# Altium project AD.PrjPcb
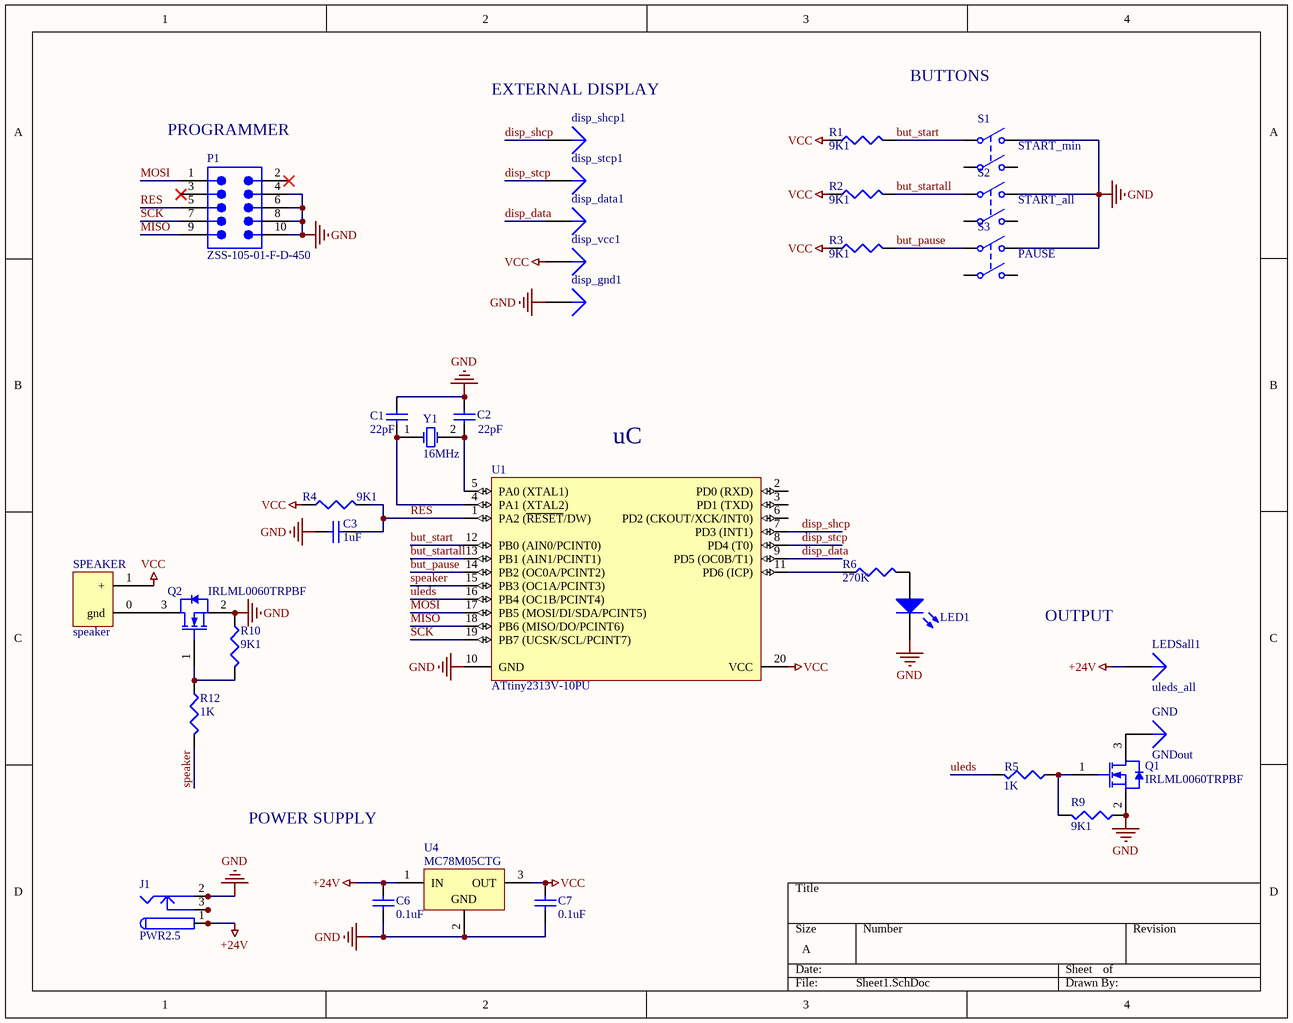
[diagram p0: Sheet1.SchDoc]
1 sheet, 33 parts. Net scope: global (net labels, ports and power ports of the same name join across sheets).
Board file: PCB1.PcbDoc

## Sheet Sheet1.SchDoc
size A

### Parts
C1  value 22pF  [CAPC1608L]  (hidden comment: Cap Semi)
C2  value 22pF  [CAPC1608L]  (hidden comment: Cap Semi)
C3  value 1uF  [CAPC1608L]  (hidden comment: Cap Semi)
C6  value 0.1uF  [CAPC1608L]  (hidden comment: Cap Semi)
C7  value 0.1uF  [CAPC1608L]  (hidden comment: Cap Semi)
disp_data1  uleds_all  [PIN1]  (value not drawn)
disp_gnd1  uleds_all  [PIN1]  (value not drawn)
disp_shcp1  uleds_all  [PIN1]  (value not drawn)
disp_stcp1  uleds_all  [PIN1]  (value not drawn)
disp_vcc1  uleds_all  [PIN1]  (value not drawn)
GND  GNDout  [PIN1]
J1  PWR2.5  [PCBComponent_1]
LED1  151051YS04000  [Type 5mm]  (value not drawn)
LEDSall1  uleds_all  [PIN1]
P1  ZSS-105-01-F-D-450  [SMTC-ZSS-105-01-X-D-450]
Q1  IRLML0060TRPBF  [NXP-SOT23_L]
Q2  IRLML0060TRPBF  [NXP-SOT23_L]
R1  value 9K1  [CAPC1608L]  (hidden comment: Res3)
R2  value 9K1  [CAPC1608L]  (hidden comment: Res3)
R3  value 9K1  [CAPC1608L]  (hidden comment: Res3)
R4  value 9K1  [CAPC1608L]  (hidden comment: Res3)
R5  value 1K  [CAPC1608L]  (hidden comment: Res3)
R6  value 270K  [CAPC1608L]  (hidden comment: Res3)
R9  value 9K1  [CAPC1608L]  (hidden comment: Res3)
R10  value 9K1  [CAPC1608L]  (hidden comment: Res3)
R12  value 1K  [CAPC1608L]  (hidden comment: Res3)
S1  START_min  [key]
S2  START_all  [key]
S3  PAUSE  [key]
SPEAKER  speaker  [speaker]
U1  ATtiny2313V-10PU  [20P3]
U4  MC78M05CTG  [TO220]
Y1  16MHz  [PCBComponent_1 - duplicate]

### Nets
+24V: C6.2 J1.1 J1.1A J1.1B LEDSall1.1 U4.1(IN)
GND: C1.1 C2.1 C3.2 C6.1 C7.1 disp_gnd1.1 J1.2 J1.2A J1.2B LED1.1(K) P1.4 P1.6 P1.8 P1.10 Q1.2(S) Q2.2(S) R9.1 R10.1 S1.2(NO1) S2.2(NO1) S3.2(NO1) U1.10(GND) U4.2(GND)
VCC: C7.2 disp_vcc1.1 R1.1 R2.1 R3.1 R4.1 SPEAKER.1(+) U1.20(VCC) U4.3(OUT)
but_pause: R3.2 S3.1(COMMON1) U1.14(PB2_(OC0A/PCINT2))
but_start: R1.2 S1.1(COMMON1) U1.12(PB0_(AIN0/PCINT0))
but_startall: R2.2 S2.1(COMMON1) U1.13(PB1_(AIN1/PCINT1))
disp_data: disp_data1.1 U1.9(PD5_(OC0B/T1))
disp_shcp: disp_shcp1.1 U1.7(PD3_(INT1))
disp_stcp: disp_stcp1.1 U1.8(PD4_(T0))
MISO: P1.9 U1.18(PB6_(MISO/DO/PCINT6))
MOSI: P1.1 U1.17(PB5_(MOSI/DI/SDA/PCINT5))
RES: C3.1 P1.5 R4.2 U1.1(PA2_(~{RESET}/DW))
SCK: P1.7 U1.19(PB7_(UCSK/SCL/PCINT7))
speaker: R12.2 U1.15(PB3_(OC1A/PCINT3))
uleds: R5.2 U1.16(PB4_(OC1B/PCINT4))
NetC1_2: C1.2 U1.4(PA1_(XTAL2)) Y1.1(OSC1)
NetC2_2: C2.2 U1.5(PA0_(XTAL1)) Y1.2(OSC2)
NetGND_1: GND.1 Q1.3(D)
NetJ1_3: J1.3 J1.3A J1.3B
NetLED1_2: LED1.2(A) R6.2
NetQ1_1: Q1.1(G) R5.1 R9.2
NetQ2_1: Q2.1(G) R10.2 R12.1
NetQ2_3: Q2.3(D) SPEAKER.0(gnd)
NetR6_1: R6.1 U1.11(PD6_(ICP))

Not connected (* = marked no-connect by the designer): P1 2* 3*; S1 3(COMMON2) 4(NO2); S2 3(COMMON2) 4(NO2); S3 3(COMMON2) 4(NO2); U1 2(PD0_(RXD)) 3(PD1_(TXD)) 6(PD2_(CKOUT/XCK/INT0))

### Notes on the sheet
- (near disp_shcp1) EXTERNAL DISPLAY
- BUTTONS
- (near P1) PROGRAMMER
- (near U1) uC
- OUTPUT
- POWER SUPPLY

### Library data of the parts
C1-C3 C6 C7 = Cap Semi: Capacitor (Semiconductor SIM Model)
disp_data1 disp_gnd1 disp_shcp1 disp_stcp1 disp_vcc1 GND LEDSall1 = Plug
J1 = PWR2.5: Low Voltage Power Supply Connector
LED1 = CMP-1488-00010-1: THT LED round mono-color color lens, WL-TMRW, Yellow; Manufacturer: Wuerth Elektronik
P1 = CMP-1024-00461-1: Manufacturer: Samtec; Pitch: 2.54 mm
Q1 Q2 = CMP-1259-00081-1: N-Channel Trench MOSFET, 60 V, 0.36 A, -55 to 150 degC, 3-Pin SOT23, Tape and Reel; PartNumber: 2N7002P,235; Manufacturer: NXP Semiconductors; ID [max] (A): 0.36; Channel Type: N; IDM [max] (A): 1.2; Automotive Qualified: Y; VGSth [typ] (V): 1.75; Packing: Tape & Reel; VDS [max] (V): 60
R1-R6 R9 R10 R12 = Res3: Resistor
S1-S3 = SW-DPST: Double-Pole, Single-Throw Switch
U1 = CMP-0093-00017-1: Low Power tinyAVR® 8-Bit Microcontroller, 2K Flash Memory, 10MHz, Industrial Temperature, 20-Lead PDIP, Pb-Free
U4 = CMP-0244-00483-1: Positive Voltage Regulator, 5V, 3-Pin TO-220
Y1 = XTAL: Crystal Oscillator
